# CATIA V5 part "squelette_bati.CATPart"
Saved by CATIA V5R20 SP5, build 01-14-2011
Part number: squelette_bati
Publications: "longueur_rail_ext", "largeur_rail_ext", "longueur_rail_int", "hauteur_rail_int", "hauteur_rail_ext", "Plan.1", "Point.1", "Point.2", "largeur_rail_int", "Point.3", "Point.4", "ouverture_rail", "Plan.2", "Point.5", "Point.6", "hauteur_pied", "hauteur_plateau", "Plan.3", "Point.7", "Point.8", "Point.9", "Point.10", "largeur_plateau", "Point.11", "Point.12", "largeur_languette", "epaisseur_languette", "Plan.4", "Point.13", "Point.14", "Point.15", "Droite.1", "Point.16", "Point.17", "Droite.2", "Plan.5"
Bounding box of the stored display mesh (mm): x -200 to 175, y -54.22 to 20, z -130 to 20
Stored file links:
  F:\iao\catia\projet iao\squelette_bati.CATPart
  F:\iao\catia\projet iao\fhartmann.CATProduct
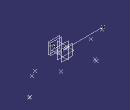
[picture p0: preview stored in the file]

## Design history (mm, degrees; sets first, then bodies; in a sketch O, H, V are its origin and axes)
Parameters
  longueur_rail_ext = 370 mm {= External.bati_longueur_rail_ext}
  largeur_rail_ext = 40 mm {= External.bati_largeur_rail_ext}
  longueur_rail_int = 350 mm {= External.bati_longueur_rail_int}
  hauteur_rail_int = 30 mm
  hauteur_rail_ext = 40 mm
  largeur_rail_int = 30 mm
  ouverture_rail = 26 mm
  hauteur_pied = 100 mm
  hauteur_plateau = 10 mm
  largeur_plateau = 100 mm {= External.bati_largeur_plateau}
  largeur_languette = 50 mm
  epaisseur_languette = 10 mm {= External.bati_epaisseur_languette}
External parameters (linked from other documents)
  External.bati_longueur_rail_ext = 370 mm
  External.bati_largeur_rail_ext = 40 mm
  External.bati_longueur_rail_int = 350 mm
  External.bati_largeur_plateau = 100 mm
  External.bati_epaisseur_languette = 10 mm
  External.bielle1_epaisseur = 6.61 mm
Set1
  Plane1: type Offset, RefPlane yz-plane, Offset 0
  Point1: type OnPlane, Support Plane1, H 20 {= largeur_rail_ext/2}, V 20 {= hauteur_rail_ext/2}, Direction (0, 1, 0)
  Point2: type OnPlane, Support Plane1, H -20 {= -largeur_rail_ext/2}, V -20 {= -hauteur_rail_ext/2}, Direction (0, 1, 0)
  Point3: type OnPlane, Support Plane1, H 15 {= largeur_rail_int /2}, V 15 {= hauteur_rail_int /2}, Direction (0, 1, 0)
  Point4: type OnPlane, Support Plane1, H -15 {= -largeur_rail_int /2}, V -15 {= -hauteur_rail_int/2}, Direction (0, 1, 0)
  Plane2: type Offset, RefPlane zx-plane, Offset 20 {= largeur_rail_ext/2}
  Point5: type OnPlane, Support Plane2, H 175 {= longueur_rail_int/2}, V 13 {= ouverture_rail/2}, Direction (-1, 0, 0)
  Point6: type OnPlane, Support Plane2, H -175 {= -longueur_rail_int/2}, V -13 {= -ouverture_rail/2}, Direction (-1, 0, 0)
  Plane3: type Offset, RefPlane zx-plane, Offset 0
  Point7: type OnPlane, Support Plane3, H 138.75 {= longueur_rail_ext/2*3/4}, V -20 {= -hauteur_rail_ext/2}, Direction (-1, 0, 0)
  Point8: type OnPlane, Support Plane3, H -138.75 {= -longueur_rail_ext/2*3/4}, V -20 {= -hauteur_rail_ext/2}, Direction (-1, 0, 0)
  Point9: type OnPlane, Support Plane3, H -161.875 {= -longueur_rail_ext/2*35/40}, V -120 {= -(hauteur_pied+hauteur_rail_ext/2)}, Direction (-1, 0, 0)
  Point10: type OnPlane, Support Plane3, H 161.875 {= longueur_rail_ext/2*35/40}, V -120 {= -(hauteur_pied+hauteur_rail_ext/2)}, Direction (-1, 0, 0)
  Point11: type OnPlane, Support Plane3, H 166.875 {= longueur_rail_ext/2*35/40+5mm}, V -130 {= -(hauteur_pied +hauteur_rail_ext/2+hauteur_plateau )}, Direction (-1, 0, 0)
  Point12: type OnPlane, Support Plane3, H -166.875 {= -(longueur_rail_ext/2*35/40+5mm)}, V -120 {= -(hauteur_rail_ext/2+hauteur_pied)}, Direction (-1, 0, 0)
  Plane4: type Offset, RefPlane Plane3, Offset 34.22 {= largeur_rail_ext/2+2*External.bielle1_epaisseur +1mm}, reversed
  Point13: type OnPlane, Support Plane4, H 25 {= largeur_languette/2}, V -120 {= -(hauteur_rail_ext/2+hauteur_pied)}, Direction (-1, 0, 0)
  Point14: type OnPlane, Support Plane4, H -25 {= -largeur_languette/2}, V 20 {= hauteur_rail_ext/2}, Direction (-1, 0, 0)
  Point15: type OnPlane, Support Plane4, H 0, V 0, Direction (-1, 0, 0)
  Line1: type Normal, RefPoint Point15, RefSkin Plane4, Start 0, End 20
  Point16: type OnPlane, Support Plane3, H 0, V 0, Direction (-1, 0, 0)
  Point17: type OnPlane, Support Plane3, H 200, V 0, Direction (-1, 0, 0)
  Line2: type PtPt, FirstPoint Point17, SecondPoint Point16
  Plane5: type Offset, RefPlane Plane4, Offset 10 {= epaisseur_languette}, reversed
Body1 (main body)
